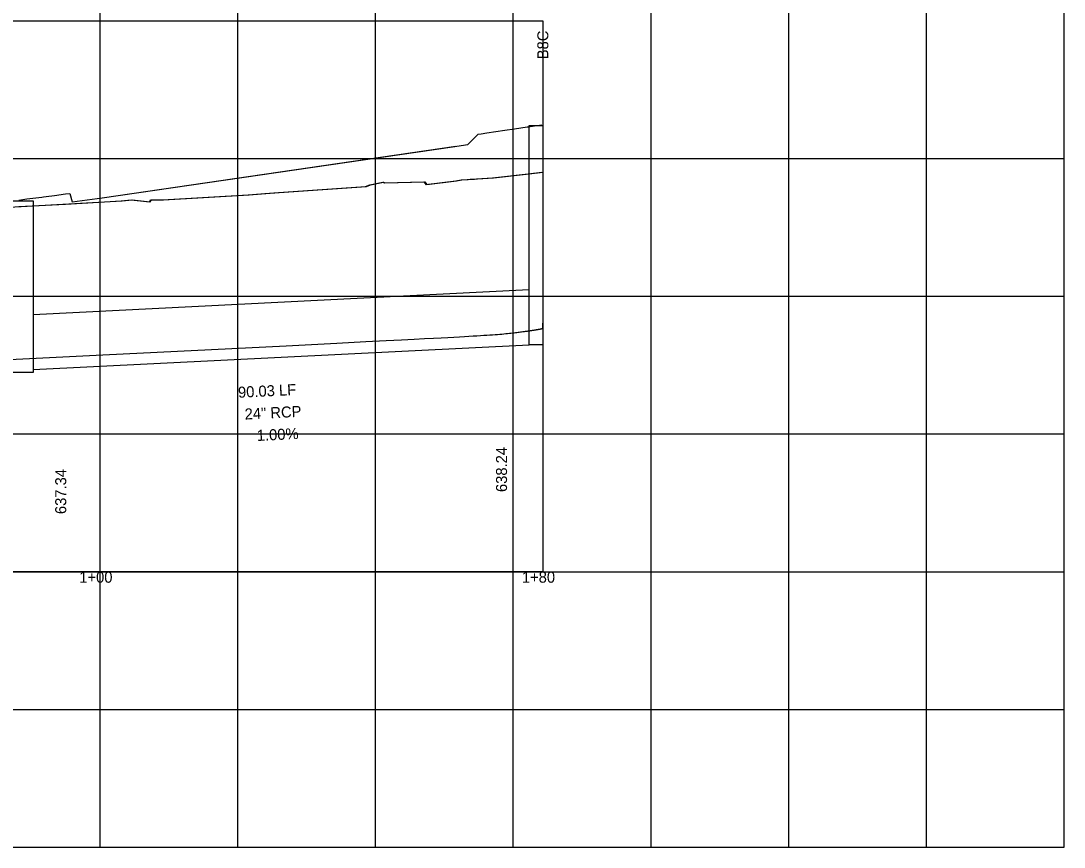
# Model space of a CAD drawing. Extents: x 2254979 to 2278074, y 13790855 to 13792793.
# Drawn here: x 2277885 to 2278074.4, y 13792491.3 to 13792641.3 of the extents above; entities that cross this region are included whole.
import ezdxf

# ---------------------------------------------------------------- set-up
doc = ezdxf.new("R2010")
doc.units = 0
for name, color, linetype in [('blank4', 7, 'Continuous'), ('BORD_grid_bottom_major_5int', 7, 'Continuous'), ('D_DRN_PROF_HGL', 7, 'Continuous'), ('D_PROF_1', 7, 'Continuous'), ('D_PROF_NOTES_1', 7, 'Continuous'), ('Default', 7, 'Continuous'), ('Drain_PipeInside', 7, 'Continuous'), ('E_Terrain', 7, 'Continuous'), ('Inlet', 7, 'Continuous'), ('z - Construction', 7, 'Continuous')]:
    doc.layers.add(name, color=color, linetype=linetype)

msp = doc.modelspace()

# ---------------------------------------------------------------- linework, layer by layer
at = {"layer": 'blank4'}
msp.add_lwpolyline([(2277799.4, 13792541.27), (2277799.4, 13792641.27), (2277979.76, 13792641.27), (2277979.76, 13792541.27)], close=True, dxfattribs=at)
at = {"layer": 'BORD_grid_bottom_major_5int'}
for p, q in [((2277899.4, 13792491.27), (2277899.4, 13792791.27)), ((2277924.4, 13792491.27), (2277924.4, 13792791.27)), ((2277949.4, 13792491.27), (2277949.4, 13792791.27)), ((2277974.4, 13792491.27), (2277974.4, 13792791.27)), ((2277999.4, 13792491.27), (2277999.4, 13792791.27)), ((2278024.4, 13792491.27), (2278024.4, 13792791.27)), ((2278049.4, 13792491.27), (2278049.4, 13792791.27)), ((2278074.4, 13792491.27), (2278074.4, 13792791.27)), ((2277749.4, 13792616.27), (2278074.4, 13792616.27)), ((2277749.4, 13792591.27), (2278074.4, 13792591.27)), ((2277749.4, 13792566.27), (2278074.4, 13792566.27)), ((2277749.4, 13792541.27), (2278074.4, 13792541.27)), ((2277749.4, 13792516.27), (2278074.4, 13792516.27)), ((2277749.4, 13792491.27), (2278074.4, 13792491.27))]:
    msp.add_line(p, q, dxfattribs=at)
at = {"layer": 'D_DRN_PROF_HGL'}
msp.add_lwpolyline([(2277881.73, 13792579.73), (2277899.85, 13792580.63), (2277933.14, 13792582.3), (2277942.34, 13792582.76), (2277947.63, 13792583.03), (2277951.31, 13792583.22), (2277954.12, 13792583.37), (2277956.39, 13792583.48), (2277958.27, 13792583.58), (2277959.88, 13792583.67), (2277961.28, 13792583.74), (2277962.52, 13792583.81), (2277963.62, 13792583.87), (2277964.62, 13792583.93), (2277965.52, 13792583.98), (2277966.34, 13792584.02), (2277967.1, 13792584.07), (2277967.8, 13792584.11), (2277968.45, 13792584.14), (2277969.05, 13792584.18), (2277969.61, 13792584.21), (2277970.13, 13792584.24), (2277970.63, 13792584.27), (2277971.09, 13792584.3), (2277971.52, 13792584.33), (2277971.93, 13792584.36), (2277972.32, 13792584.4), (2277972.69, 13792584.45), (2277973.03, 13792584.49), (2277973.36, 13792584.52), (2277973.68, 13792584.56), (2277973.98, 13792584.59), (2277974.26, 13792584.63), (2277974.53, 13792584.66), (2277974.78, 13792584.69), (2277975.03, 13792584.72), (2277975.26, 13792584.75), (2277975.49, 13792584.78), (2277975.7, 13792584.8), (2277975.9, 13792584.83), (2277976.1, 13792584.85), (2277976.28, 13792584.88), (2277976.46, 13792584.9), (2277976.63, 13792584.92), (2277976.8, 13792584.94), (2277976.95, 13792584.96), (2277977.1, 13792584.98), (2277977.24, 13792585), (2277977.38, 13792585.02), (2277977.51, 13792585.04), (2277977.64, 13792585.06), (2277977.76, 13792585.07), (2277977.87, 13792585.09), (2277977.98, 13792585.11), (2277978.09, 13792585.12), (2277978.19, 13792585.14), (2277978.29, 13792585.15), (2277978.38, 13792585.17), (2277978.47, 13792585.18), (2277978.55, 13792585.19), (2277978.63, 13792585.21), (2277978.71, 13792585.22), (2277978.78, 13792585.23), (2277978.85, 13792585.24), (2277978.92, 13792585.25), (2277978.98, 13792585.27), (2277979.04, 13792585.28), (2277979.1, 13792585.29), (2277979.15, 13792585.3), (2277979.2, 13792585.31), (2277979.25, 13792585.32), (2277979.3, 13792585.33), (2277979.34, 13792585.34), (2277979.38, 13792585.35), (2277979.42, 13792585.35), (2277979.45, 13792585.36), (2277979.49, 13792585.37), (2277979.52, 13792585.38), (2277979.55, 13792585.39), (2277979.58, 13792585.39), (2277979.6, 13792585.4), (2277979.62, 13792585.41), (2277979.65, 13792585.42), (2277979.66, 13792585.42), (2277979.68, 13792585.43), (2277979.7, 13792585.44), (2277979.71, 13792585.44), (2277979.72, 13792585.45), (2277979.73, 13792585.46), (2277979.74, 13792585.46), (2277979.75, 13792585.47), (2277979.75, 13792585.47), (2277979.76, 13792585.48), (2277979.76, 13792585.48), (2277979.76, 13792586.38)], dxfattribs=at)
at = {"layer": 'D_PROF_1'}
msp.add_line((2277899.78, 13792609.17), (2277963.98, 13792618.51), dxfattribs=at)
msp.add_lwpolyline([(2277884.6, 13792608.74), (2277886.08, 13792608.93), (2277888.79, 13792609.28), (2277889.08, 13792609.31), (2277889.6, 13792609.38), (2277891.11, 13792609.58), (2277893.1, 13792609.84), (2277893.1, 13792609.84), (2277893.89, 13792609.94), (2277894.28, 13792608.43), (2277897.03, 13792608.79), (2277899.78, 13792609.17), (2277963.38, 13792618.42), (2277966.13, 13792618.84), (2277968.01, 13792620.68), (2277968.57, 13792620.77), (2277969.6, 13792620.92), (2277972.84, 13792621.41), (2277974.6, 13792621.67), (2277976.94, 13792622.02), (2277977.1, 13792622.05), (2277977.1, 13792622.05), (2277978.22, 13792622.21), (2277978.71, 13792622.29), (2277979.6, 13792622.42)], dxfattribs=at)
at = {"layer": 'Default'}
msp.add_line((2277899.4, 13792541.27), (2277899.4, 13792641.27), dxfattribs=at)
at = {"layer": 'Drain_PipeInside'}
for p, q in [((2277887.23, 13792587.97), (2277977.26, 13792592.47)), ((2277887.23, 13792577.97), (2277977.26, 13792582.47))]:
    msp.add_line(p, q, dxfattribs=at)
at = {"layer": 'E_Terrain'}
for points in [[(2277881.73, 13792607.38), (2277887.23, 13792607.69), (2277887.23, 13792607.69), (2277903.36, 13792608.58), (2277905.18, 13792608.79), (2277908.48, 13792608.41), (2277908.5, 13792608.44), (2277908.72, 13792608.76), (2277910.88, 13792608.76), (2277926.44, 13792609.66), (2277929.44, 13792609.92), (2277931.92, 13792610.11), (2277947.74, 13792611.21), (2277948.49, 13792611.5), (2277950.86, 13792611.98), (2277951.09, 13792611.89), (2277958.35, 13792612.07), (2277958.68, 13792611.57), (2277964.1, 13792612.22), (2277965.08, 13792612.41), (2277966.18, 13792612.48), (2277966.71, 13792612.51), (2277967.2, 13792612.54), (2277967.37, 13792612.52), (2277967.87, 13792612.56), (2277970.81, 13792612.77), (2277977.26, 13792613.52), (2277977.26, 13792613.52), (2277979.76, 13792613.81)], [(2277884.6, 13792607.55), (2277893.1, 13792608.02), (2277893.1, 13792608.02), (2277903.2, 13792608.58), (2277905.02, 13792608.79), (2277908.32, 13792608.41), (2277908.34, 13792608.44), (2277908.56, 13792608.76), (2277910.72, 13792608.76), (2277926.28, 13792609.66), (2277929.28, 13792609.92), (2277931.76, 13792610.11), (2277947.58, 13792611.21), (2277948.33, 13792611.5), (2277950.71, 13792611.98), (2277950.93, 13792611.89), (2277958.18, 13792612.07), (2277958.51, 13792611.57), (2277963.94, 13792612.22), (2277964.92, 13792612.41), (2277966.02, 13792612.48), (2277966.55, 13792612.51), (2277967.04, 13792612.54), (2277967.21, 13792612.52), (2277967.71, 13792612.56), (2277970.65, 13792612.77), (2277977.1, 13792613.52), (2277977.1, 13792613.52), (2277979.6, 13792613.81)]]:
    msp.add_lwpolyline(points, dxfattribs=at)
at = {"layer": 'Inlet'}
for points in [[(2277977.26, 13792622.27), (2277979.76, 13792622.27), (2277979.76, 13792582.47), (2277977.26, 13792582.47)], [(2277878.41, 13792608.59), (2277887.23, 13792608.59), (2277887.23, 13792577.44), (2277878.41, 13792577.44)]]:
    msp.add_lwpolyline(points, close=True, dxfattribs=at)
at = {"layer": 'z - Construction'}
for p, q in [((2277799.4, 13792616.27), (2277979.76, 13792616.27)), ((2277799.4, 13792591.27), (2277979.76, 13792591.27)), ((2277799.4, 13792566.27), (2277979.76, 13792566.27))]:
    msp.add_line(p, q, dxfattribs=at)

# ---------------------------------------------------------------- texts
at = {"layer": 'D_PROF_NOTES_1'}
for s, rotation, p in [('B8C', 90, (2277980.76, 13792634.3)), ('90.03 LF', 2.8624, (2277924.47, 13792572.83)), ('24" RCP', 2.8624, (2277925.68, 13792568.88)), ('1.00%', 2.8624, (2277927.88, 13792564.99)), ('638.24', 90, (2277973.26, 13792555.73)), ('637.34', 90, (2277893.23, 13792551.73))]:
    msp.add_text(s, height=2, rotation=rotation, dxfattribs=at).set_placement(p)
at = {"layer": 'Default'}
for s, p in [('1+00', (2277895.6, 13792539.27)), ('1+80', (2277975.96, 13792539.27))]:
    msp.add_text(s, height=2, dxfattribs=at).set_placement(p)

doc.saveas('drawing.dxf')
